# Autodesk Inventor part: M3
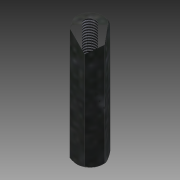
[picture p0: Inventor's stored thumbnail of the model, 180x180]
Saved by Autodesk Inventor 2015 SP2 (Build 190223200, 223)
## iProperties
Created: 2012-08
Part Number: M3
Material: Stahl
Document SubType Name: Modeling
Designer: rYan
Density: 7.85 g/cm^3
Mass: 3.36246 g
Surface Area: 5.74911 cm^2
Volume: 0.428339 cm^3
Appearance: Platte
Author: rYan
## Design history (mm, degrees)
derived "Abstandsbolzen Typ A.ipt"
feature "Volumenkörper1::Abstandsbolzen Typ A.ipt"
tag "Bezeichnung1"
node "Volumenkörper1"
other parameters: "SW" = 5.5, "L" = 25, "d2" = 0, "d16" = 45 deg
